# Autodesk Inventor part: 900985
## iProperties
Created: 2007-10
Part Number: 900985
Document SubType Name: Sheet Metal
Designer: TH
Density: 8.08 g/cm^3
Mass: 55.7852 g
Surface Area: 142.634 cm^2
Volume: 6.9041 cm^3
Material: Stainless Steel
Description: MOTOR SLEEVE
Sheet Metal Rule: Default
Component Category: Electrical
Author: TH
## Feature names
1. Extrusion1
2. Extrusion2
3. Mirror1
4. Cut1
